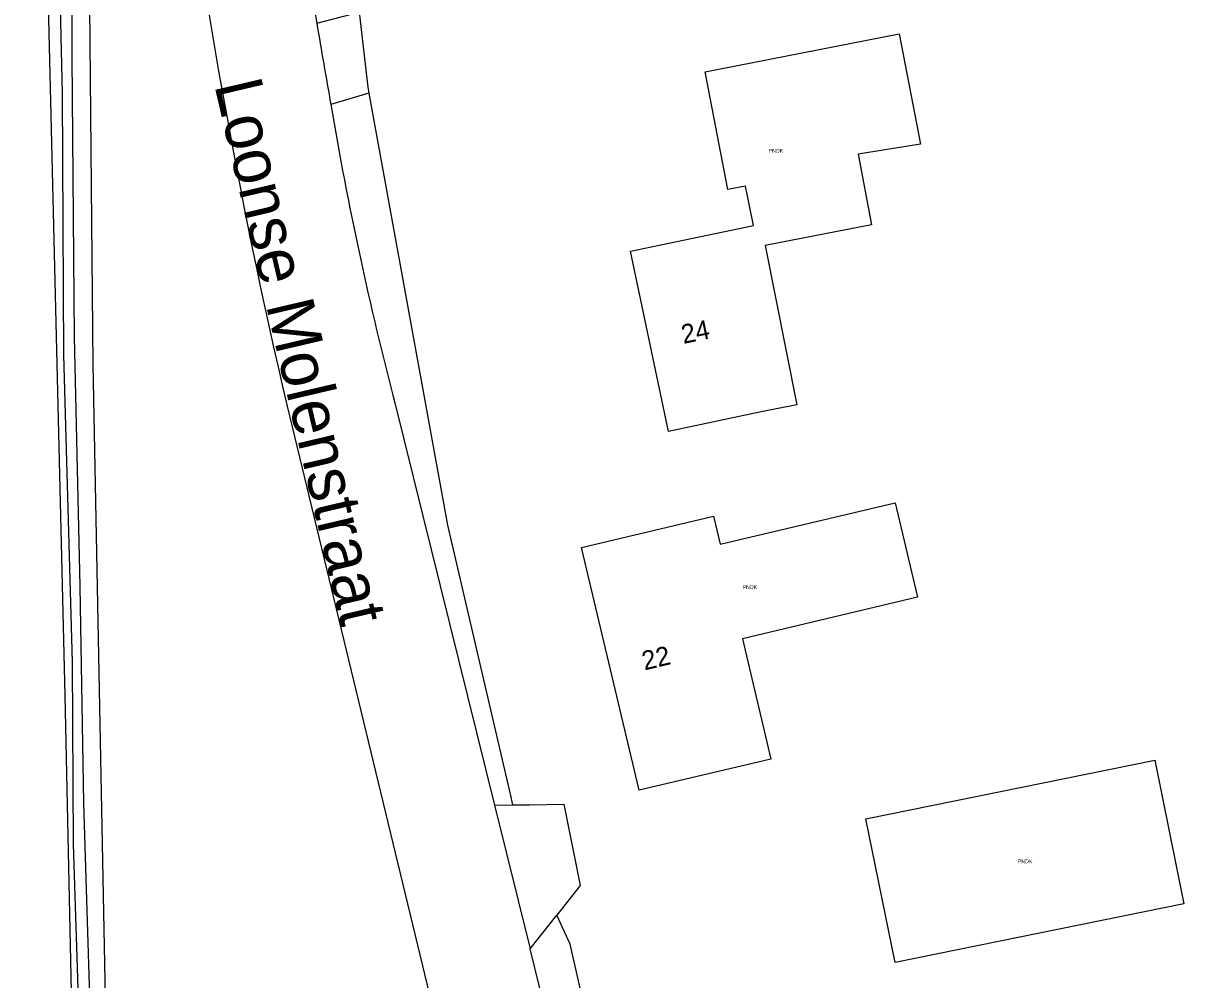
# Model space of a CAD drawing. Extents: x 134297 to 137000, y 403500 to 406000.
# Drawn here: x 135048.4 to 135109.5, y 403540.6 to 403590.9 of the extents above; entities that cross this region are included whole.
import ezdxf

# ---------------------------------------------------------------- set-up
doc = ezdxf.new("R2010")
doc.units = 0
for name, color, linetype in [('gg-anno-huisnummerreeks BGT', 7, 'Continuous'), ('gg-anno-openbare ruimte label', 7, 'Continuous'), ('gx-grn-maaiveld', 7, 'Continuous'), ('kenmerkpunt-x pandkandidaat', 7, 'Continuous')]:
    doc.layers.add(name, color=color, linetype=linetype)

msp = doc.modelspace()

# ---------------------------------------------------------------- linework, layer by layer
at = {"layer": 'gx-grn-maaiveld'}
for p, q in [((135063.823, 403590.922), (135066.058, 403591.501)), ((135066.56, 403587.233), (135064.563, 403586.645)), ((135062.261, 403570.76), (135070.881, 403535.18)), ((135067.952, 403570.864), (135073.179, 403549.768)), ((135073.179, 403549.768), (135074.131, 403549.779)), ((135073.179, 403549.768), (135075.051, 403542.196)), ((135075.051, 403542.196), (135076.463, 403543.981)), ((135079.665, 403523.534), (135075.051, 403542.196))]:
    msp.add_line(p, q, dxfattribs=at)
for points in [[(135051.547, 403636.977), (135051.729, 403605.035), (135052.037, 403572.947), (135052.671, 403539.629)], [(135048.364, 403630.258), (135049.411, 403602.803), (135050.564, 403555.535), (135051.255, 403522.678), (135051.179, 403517.029), (135051.382, 403505.111)], [(135050.103, 403600.862), (135050.41, 403587.22), (135050.487, 403573.462), (135050.948, 403557.284), (135050.986, 403547.715), (135051.255, 403539.568), (135051.601, 403525.887), (135051.793, 403517.586), (135051.909, 403505.712), (135052.043, 403505.328), (135052.389, 403505.251), (135052.697, 403505.404), (135052.773, 403505.789), (135052.447, 403521.41), (135052.024, 403534.341), (135051.96, 403536.513)], [(135051.882, 403539.135), (135051.563, 403549.867), (135051.371, 403561.28), (135051.063, 403574.423), (135050.948, 403589.141), (135050.91, 403600.247)], [(135066.058, 403591.501), (135066.501, 403587.558), (135066.56, 403587.233)], [(135085.468, 403582.169), (135084.264, 403588.37), (135094.489, 403590.356), (135095.615, 403584.561), (135092.324, 403584.024), (135093.02, 403580.315), (135087.424, 403579.219), (135089.096, 403570.833), (135087.222, 403570.46), (135082.332, 403569.43), (135080.342, 403578.919), (135086.817, 403580.268), (135086.39, 403582.347), (135085.468, 403582.169)], [(135066.56, 403587.233), (135070.704, 403564.501), (135073.999, 403550.345), (135074.131, 403549.779)], [(135085.06, 403563.494), (135094.275, 403565.685), (135095.456, 403560.718), (135086.235, 403558.526), (135087.733, 403552.191), (135080.801, 403550.551), (135077.761, 403563.329), (135084.707, 403564.984), (135085.06, 403563.494)], [(135109.47, 403544.567), (135094.266, 403541.483), (135092.733, 403549.045), (135107.937, 403552.129), (135109.47, 403544.567)], [(135074.131, 403549.779), (135075.019, 403549.789), (135076.834, 403549.81), (135077.692, 403545.533), (135076.463, 403543.981)], [(135082.867, 403517.419), (135082.653, 403518.282), (135077.159, 403542.442), (135076.463, 403543.981)]]:
    msp.add_lwpolyline(points, dxfattribs=at)
for centre, radius, start, end in [((135371.587, 403643.227), 317.702, 180.88901, 193.18516), ((135291.038, 403628.977), 230.38, 189.09725, 189.50804), ((135386.899, 403644.618), 327.508, 189.43637, 190.19573), ((135241.021, 403616.285), 178.93, 189.53517, 194.70542)]:
    msp.add_arc(centre, radius, start, end, dxfattribs=at)

# ---------------------------------------------------------------- texts
at = {"layer": 'gg-anno-huisnummerreeks BGT'}
for s, rotation, p in [('24', 11.9, (135083.127, 403574.039)), ('22', 13.4, (135081.073, 403556.853))]:
    msp.add_text(s, height=1, rotation=rotation, dxfattribs=at).set_placement(p)
at = {"layer": 'gg-anno-openbare ruimte label'}
msp.add_text('Loonse Molenstraat', height=2.5, rotation=283.2, dxfattribs=at).set_placement((135058.419, 403587.684))
at = {"layer": 'kenmerkpunt-x pandkandidaat'}
for p in [(135087.608, 403584.11), (135086.238, 403561.139), (135100.731, 403546.707)]:
    msp.add_text('PNDK', height=0.2, dxfattribs=at).set_placement(p)

doc.saveas('drawing.dxf')
